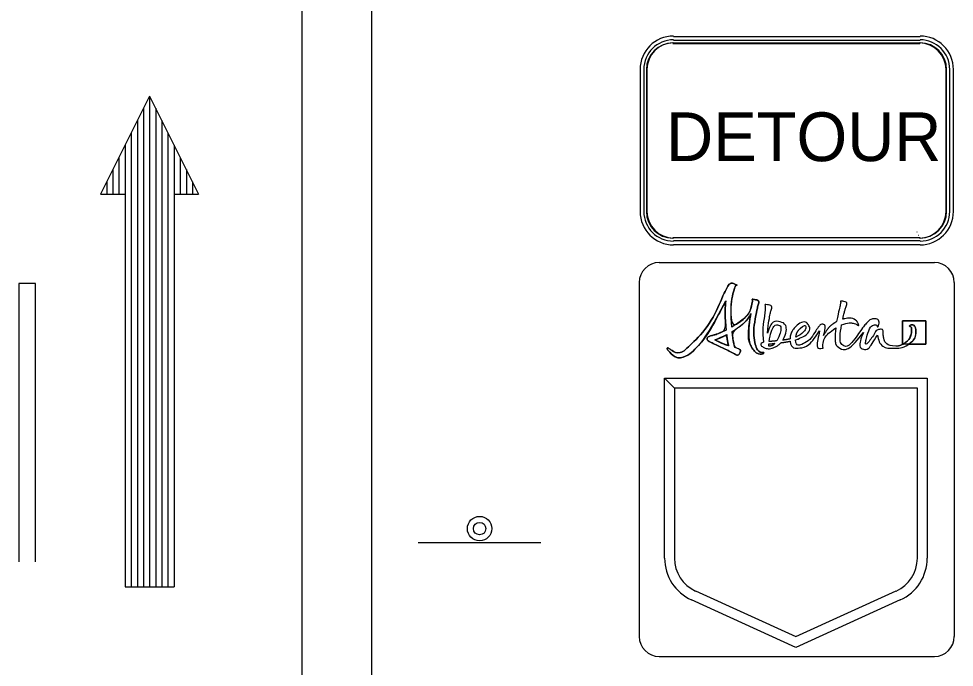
# Model space of a CAD drawing. Extents: x 1806 to 2022, y 110 to 389.
# Drawn here: x 1969.34 to 1985.61, y 233.48 to 244.76 of the extents above; entities that cross this region are included whole.
import ezdxf

# ---------------------------------------------------------------- set-up
doc = ezdxf.new("R2010")
doc.units = 0
for name, color, linetype in [('Level 10', 7, 'Continuous'), ('Level 2', 7, 'Continuous'), ('Level 44', 7, 'Continuous'), ('Level 50', 7, 'Continuous'), ('Level 53', 7, 'Continuous')]:
    doc.layers.add(name, color=color, linetype=linetype)

msp = doc.modelspace()

# ---------------------------------------------------------------- linework, layer by layer
at = {"layer": 'Level 10'}
for p, q in [((1974.267, 233.074), (1974.267, 272.1)), ((1975.477, 233.074), (1975.477, 272.1))]:
    msp.add_line(p, q, dxfattribs=at)
at = {"layer": 'Level 2'}
for p, q in [((1980.475, 240.516), (1985.26, 240.516)), ((1980.475, 240.516), (1985.26, 240.516)), ((1969.337, 240.152), (1969.337, 235.314)), ((1969.627, 240.152), (1969.337, 240.152)), ((1969.627, 235.314), (1969.627, 240.152)), ((1980.128, 240.169), (1980.128, 234.014)), ((1985.607, 240.169), (1985.607, 234.014)), ((1980.57, 235.376), (1980.57, 238.504)), ((1980.57, 238.504), (1980.742, 238.332)), ((1980.742, 238.332), (1980.57, 238.504)), ((1980.57, 238.504), (1985.136, 238.504)), ((1985.136, 238.504), (1985.136, 235.376)), ((1980.742, 238.332), (1980.742, 235.376)), ((1984.965, 238.332), (1980.742, 238.332)), ((1984.965, 235.376), (1984.965, 238.332)), ((1981.109, 234.805), (1982.853, 234.012)), ((1982.853, 234.012), (1984.597, 234.805)), ((1982.853, 233.824), (1981.039, 234.649)), ((1984.668, 234.649), (1982.853, 233.824)), ((1980.475, 233.667), (1985.26, 233.667))]:
    msp.add_line(p, q, dxfattribs=at)
for centre, radius, start, end in [((1980.475, 240.169), 0.347, 90, 180), ((1985.26, 240.169), 0.347, 0, 90), ((1981.369, 235.376), 0.799, 180, 245.5432), ((1981.369, 235.376), 0.628, 180, 245.5432), ((1984.337, 235.376), 0.628, 294.4568, 0), ((1984.337, 235.376), 0.799, 294.4568, 0), ((1980.475, 234.014), 0.347, 180, 270), ((1985.26, 234.014), 0.347, 270, 0)]:
    msp.add_arc(centre, radius, start, end, dxfattribs=at)
at = {"layer": 'Level 44'}
for p, q in [((1980.724, 244.449), (1985.015, 244.449)), ((1980.724, 244.384), (1985.015, 244.384)), ((1980.714, 244.328), (1985.005, 244.328)), ((1980.72, 244.336), (1985.011, 244.336)), ((1980.724, 244.33), (1985.015, 244.33)), ((1980.724, 244.33), (1985.015, 244.33)), ((1980.149, 241.409), (1980.149, 243.874)), ((1980.214, 241.409), (1980.214, 243.874)), ((1980.258, 241.407), (1980.258, 243.872)), ((1980.268, 241.409), (1980.268, 243.874)), ((1980.268, 241.409), (1980.268, 243.874)), ((1980.268, 241.409), (1980.268, 243.874)), ((1985.457, 243.872), (1985.457, 241.407)), ((1985.467, 243.874), (1985.467, 241.409)), ((1985.467, 243.874), (1985.467, 241.409)), ((1985.467, 243.874), (1985.467, 241.409)), ((1985.521, 243.874), (1985.521, 241.409)), ((1985.586, 243.874), (1985.586, 241.409)), ((1984.958, 241.05), (1984.962, 241.052)), ((1984.987, 240.992), (1984.991, 240.994)), ((1985.005, 240.944), (1980.714, 240.944)), ((1985.015, 240.946), (1980.724, 240.946)), ((1985.015, 240.946), (1980.724, 240.946)), ((1985.015, 240.946), (1980.724, 240.946)), ((1985.015, 240.892), (1980.724, 240.892)), ((1985.015, 240.827), (1980.724, 240.827)), ((1983.08, 240.938), (1983.08, 240.938)), ((1983.09, 240.94), (1983.09, 240.94)), ((1983.09, 240.94), (1983.09, 240.94)), ((1983.09, 240.94), (1983.09, 240.94)), ((1985.011, 240.944), (1985.015, 240.946)), ((1976.282, 235.651), (1978.415, 235.651))]:
    msp.add_line(p, q, dxfattribs=at)
for radius in [0.213, 0.107]:
    msp.add_circle((1977.353, 235.889), radius, dxfattribs=at)
for centre, radius, start, end in [((1980.724, 243.875), 0.581, 90, 180), ((1980.724, 243.875), 0.516, 90, 180), ((1985.011, 243.875), 0.581, 0, 90), ((1985.011, 243.875), 0.516, 0, 90), ((1980.714, 243.873), 0.462, 90, 180), ((1980.724, 243.875), 0.462, 90, 180), ((1980.724, 243.875), 0.462, 90, 180), ((1980.724, 243.875), 0.462, 90, 180), ((1985.001, 243.873), 0.462, 0, 90), ((1985.011, 243.875), 0.462, 0, 90), ((1985.011, 243.875), 0.462, 0, 90), ((1985.011, 243.875), 0.462, 0, 90), ((1980.724, 241.405), 0.581, 180, 270), ((1980.724, 241.405), 0.516, 180, 270), ((1980.714, 241.403), 0.462, 180, 270), ((1980.724, 241.405), 0.462, 180, 270), ((1980.724, 241.405), 0.462, 180, 270), ((1980.724, 241.405), 0.462, 180, 270), ((1985.001, 241.403), 0.462, 270, 0), ((1985.011, 241.405), 0.462, 270, 0), ((1985.011, 241.405), 0.462, 270, 0), ((1985.011, 241.405), 0.581, 270, 0), ((1985.011, 241.405), 0.516, 270, 0), ((1985.011, 241.405), 0.462, 270, 0)]:
    msp.add_arc(centre, radius, start, end, dxfattribs=at)
at = {"layer": 'Level 50'}
for p, q in [((1971.613, 243.413), (1970.76, 241.706)), ((1971.613, 243.413), (1971.613, 234.88)), ((1971.613, 243.413), (1972.466, 241.706)), ((1971.507, 243.199), (1971.507, 234.88)), ((1971.72, 243.199), (1971.72, 234.88)), ((1971.4, 242.986), (1971.4, 234.88)), ((1971.827, 242.986), (1971.827, 234.88)), ((1971.293, 242.773), (1971.293, 234.88)), ((1971.933, 242.773), (1971.933, 234.88)), ((1971.187, 242.559), (1971.187, 234.88)), ((1972.04, 242.559), (1972.04, 234.88)), ((1971.08, 242.346), (1971.08, 241.706)), ((1972.146, 242.346), (1972.146, 241.706)), ((1970.973, 242.133), (1970.973, 241.706)), ((1972.253, 242.133), (1972.253, 241.706)), ((1970.867, 241.919), (1970.867, 241.706)), ((1972.36, 241.919), (1972.36, 241.706)), ((1970.76, 241.706), (1971.187, 241.706)), ((1971.187, 241.706), (1971.187, 234.88)), ((1972.04, 241.706), (1972.04, 234.88)), ((1972.04, 241.706), (1972.466, 241.706)), ((1971.187, 234.88), (1972.04, 234.88))]:
    msp.add_line(p, q, dxfattribs=at)
at = {"layer": 'Level 53'}
msp.add_line((1984.816, 239.099), (1984.716, 239.099), dxfattribs=at)
msp.add_lwpolyline([(1984.816, 239.099), (1985.111, 239.099), (1985.111, 239.506), (1984.704, 239.506), (1984.704, 239.099), (1984.716, 239.099)], dxfattribs=at)
for points, degree in [([(1982.262, 238.951), (1982.218, 238.958), (1982.161, 239.017), (1982.143, 239.115), (1982.112, 239.292), (1982.131, 239.466), (1982.183, 239.726), (1982.192, 239.775), (1982.226, 239.86), (1982.119, 239.876), (1982.085, 239.881), (1982.103, 239.865), (1982.093, 239.82), (1982.053, 239.626), (1981.894, 239.487), (1981.736, 239.394), (1981.719, 239.615), (1981.726, 239.861), (1981.768, 240.012), (1981.803, 240.139), (1981.845, 240.115), (1981.793, 240.142), (1981.738, 240.17), (1981.679, 240.133), (1981.632, 240.038), (1981.585, 239.944), (1981.366, 239.429), (1981.017, 239.082), (1980.838, 238.905), (1980.677, 238.996), (1980.644, 239.023), (1980.618, 239.046), (1980.608, 239.011), (1980.641, 238.976), (1980.786, 238.82), (1980.997, 238.91), (1981.073, 238.987), (1981.286, 239.199), (1981.533, 239.656), (1981.633, 239.85), (1981.623, 239.741), (1981.62, 239.557), (1981.641, 239.343), (1981.532, 239.29), (1981.436, 239.259), (1981.39, 239.247), (1981.34, 239.234), (1981.31, 239.214), (1981.309, 239.191), (1981.308, 239.166), (1981.341, 239.145), (1981.389, 239.122), (1981.475, 239.081), (1981.725, 238.963), (1981.787, 238.927), (1981.84, 238.896), (1981.866, 238.92), (1981.881, 238.954), (1981.902, 238.997), (1981.846, 239.022), (1981.791, 239.038), (1981.77, 239.111), (1981.754, 239.208), (1981.743, 239.316), (1981.87, 239.394), (1981.995, 239.499), (1982.068, 239.629), (1982.049, 239.52), (1982.003, 239.149), (1982.12, 238.993), (1982.146, 238.958), (1982.203, 238.92), (1982.258, 238.926), (1982.284, 238.929), (1982.298, 238.946), (1982.295, 238.951), (1982.292, 238.957), (1982.277, 238.949), (1982.262, 238.951)], 3), ([(1981.736, 239.394), (1981.719, 239.615), (1981.726, 239.861), (1981.768, 240.012), (1981.803, 240.139), (1981.845, 240.115), (1981.793, 240.142), (1981.738, 240.17), (1981.679, 240.133), (1981.632, 240.038), (1981.585, 239.944), (1981.366, 239.429), (1981.017, 239.082), (1980.838, 238.905), (1980.677, 238.996), (1980.644, 239.023), (1980.618, 239.046), (1980.608, 239.011), (1980.641, 238.976), (1980.786, 238.82), (1980.997, 238.91), (1981.073, 238.987), (1981.286, 239.199), (1981.533, 239.656), (1981.633, 239.85)], 3), ([(1981.633, 239.85), (1981.623, 239.741), (1981.62, 239.557), (1981.641, 239.343)], 2), ([(1982.262, 238.951), (1982.218, 238.958), (1982.161, 239.017), (1982.143, 239.115), (1982.112, 239.292), (1982.131, 239.466), (1982.183, 239.726), (1982.192, 239.775), (1982.226, 239.86), (1982.119, 239.876), (1982.085, 239.881), (1982.103, 239.865), (1982.093, 239.82), (1982.053, 239.626), (1981.894, 239.487), (1981.736, 239.394)], 3), ([(1983.667, 239.532), (1983.678, 239.587), (1983.692, 239.642), (1983.707, 239.696), (1983.721, 239.745), (1983.761, 239.83), (1983.656, 239.846), (1983.623, 239.851), (1983.637, 239.835), (1983.626, 239.79), (1983.605, 239.706), (1983.58, 239.598), (1983.561, 239.489)], 3), ([(1982.36, 239.288), (1982.368, 239.391), (1982.385, 239.518), (1982.408, 239.635), (1982.418, 239.684), (1982.452, 239.769), (1982.345, 239.786), (1982.311, 239.791), (1982.317, 239.775), (1982.319, 239.729), (1982.323, 239.668), (1982.255, 239.295), (1982.291, 239.132)], 3), ([(1981.743, 239.316), (1981.87, 239.394), (1981.995, 239.499), (1982.068, 239.629)], 2), ([(1982.068, 239.629), (1982.049, 239.52), (1982.003, 239.149), (1982.12, 238.993), (1982.146, 238.958), (1982.203, 238.92), (1982.258, 238.926), (1982.284, 238.929), (1982.298, 238.946), (1982.295, 238.951), (1982.292, 238.957), (1982.277, 238.949), (1982.262, 238.951)], 3), ([(1982.623, 239.167), (1982.698, 239.29), (1982.692, 239.456), (1982.581, 239.484), (1982.452, 239.516), (1982.387, 239.391), (1982.36, 239.288)], 3), ([(1984.59, 239.063), (1984.423, 239.063), (1984.379, 239.193), (1984.371, 239.257), (1984.366, 239.3), (1984.375, 239.362), (1984.301, 239.354), (1984.25, 239.348), (1984.203, 239.247), (1984.137, 239.162), (1984.081, 239.09), (1984.056, 239.096), (1984.069, 239.159), (1984.085, 239.237), (1984.151, 239.421), (1984.225, 239.434), (1984.26, 239.44), (1984.272, 239.38), (1984.288, 239.418), (1984.304, 239.456), (1984.289, 239.538), (1984.212, 239.538), (1984.158, 239.538), (1984.093, 239.48), (1984.04, 239.415), (1983.993, 239.358), (1983.759, 239.013), (1983.66, 239.087), (1983.614, 239.122), (1983.618, 239.264), (1983.647, 239.431)], 3), ([(1983.647, 239.431), (1983.764, 239.476), (1983.861, 239.462), (1983.916, 239.435), (1983.943, 239.422), (1983.947, 239.424), (1983.935, 239.454), (1983.918, 239.498), (1983.824, 239.566), (1983.677, 239.535), (1983.674, 239.534), (1983.67, 239.533), (1983.667, 239.532)], 3), ([(1984.704, 239.506), (1984.704, 239.506), (1984.704, 239.099), (1984.704, 239.099), (1984.704, 239.099), (1984.716, 239.099), (1984.716, 239.099), (1984.804, 239.152), (1984.863, 239.253), (1984.863, 239.336), (1984.863, 239.408), (1984.825, 239.405), (1984.829, 239.415), (1984.842, 239.444), (1984.932, 239.427), (1984.937, 239.326), (1984.941, 239.239), (1984.896, 239.156), (1984.816, 239.099), (1984.816, 239.099), (1985.111, 239.099), (1985.111, 239.099), (1985.111, 239.099), (1985.111, 239.506), (1985.111, 239.506), (1985.111, 239.506), (1984.704, 239.506), (1984.704, 239.506)], 3), ([(1981.641, 239.343), (1981.532, 239.29), (1981.436, 239.259), (1981.39, 239.247), (1981.34, 239.234), (1981.31, 239.214), (1981.309, 239.191), (1981.308, 239.166), (1981.341, 239.145), (1981.389, 239.122), (1981.475, 239.081), (1981.725, 238.963), (1981.787, 238.927), (1981.84, 238.896), (1981.866, 238.92), (1981.881, 238.954), (1981.902, 238.997), (1981.846, 239.022), (1981.791, 239.038)], 3), ([(1982.387, 239.143), (1982.405, 239.274), (1982.473, 239.456), (1982.557, 239.426), (1982.606, 239.41), (1982.581, 239.256), (1982.518, 239.155)], 3), ([(1982.846, 239.171), (1982.864, 239.176), (1982.88, 239.182), (1982.893, 239.188), (1983.054, 239.259), (1983.11, 239.367), (1983.069, 239.433), (1983.03, 239.495), (1982.919, 239.476), (1982.831, 239.384), (1982.788, 239.338), (1982.754, 239.26), (1982.75, 239.188)], 3), ([(1983.335, 239.247), (1983.345, 239.297), (1983.361, 239.353), (1983.362, 239.391), (1983.363, 239.43), (1983.336, 239.439), (1983.325, 239.442), (1983.302, 239.449), (1983.275, 239.437), (1983.247, 239.399), (1983.182, 239.308), (1983.101, 239.164), (1982.977, 239.104), (1982.888, 239.06), (1982.849, 239.104), (1982.846, 239.171)], 3), ([(1982.933, 239.375), (1982.987, 239.425), (1983.014, 239.422), (1983.021, 239.408), (1983.036, 239.379), (1982.972, 239.277), (1982.851, 239.22)], 3), ([(1982.851, 239.22), (1982.861, 239.276), (1982.89, 239.336), (1982.933, 239.375)], 2), ([(1983.26, 239.327), (1983.25, 239.229), (1983.186, 239.015), (1983.295, 239.026), (1983.338, 239.03), (1983.319, 239.037), (1983.322, 239.074), (1983.331, 239.203), (1983.439, 239.312), (1983.545, 239.379)], 3), ([(1983.561, 239.489), (1983.475, 239.439), (1983.394, 239.356), (1983.335, 239.247)], 2), ([(1983.545, 239.379), (1983.527, 239.221), (1983.533, 239.08), (1983.605, 239.035), (1983.737, 238.953), (1983.923, 239.17), (1984.026, 239.303)], 3), ([(1984.716, 239.099), (1984.804, 239.152), (1984.863, 239.253), (1984.863, 239.336), (1984.863, 239.408), (1984.825, 239.405), (1984.829, 239.415), (1984.842, 239.444), (1984.932, 239.427), (1984.937, 239.326), (1984.941, 239.239), (1984.896, 239.156), (1984.816, 239.099)], 3), ([(1981.445, 239.173), (1981.502, 239.193), (1981.573, 239.223), (1981.649, 239.263)], 2), ([(1981.445, 239.173), (1981.502, 239.193), (1981.573, 239.223), (1981.649, 239.263), (1981.659, 239.177), (1981.67, 239.114), (1981.683, 239.068), (1981.627, 239.088), (1981.548, 239.12), (1981.445, 239.173)], 3), ([(1981.683, 239.068), (1981.627, 239.088), (1981.548, 239.12), (1981.445, 239.173)], 2), ([(1981.649, 239.263), (1981.659, 239.177), (1981.67, 239.114), (1981.683, 239.068)], 2), ([(1981.791, 239.038), (1981.77, 239.111), (1981.754, 239.208), (1981.743, 239.316)], 2), ([(1982.75, 239.188), (1982.713, 239.18), (1982.67, 239.173), (1982.623, 239.167)], 2), ([(1982.752, 239.148), (1982.76, 239.076), (1982.807, 239.021), (1982.916, 239.031), (1983.071, 239.046), (1983.208, 239.236), (1983.26, 239.327)], 3), ([(1984.026, 239.303), (1983.974, 239.185), (1983.944, 239.034), (1984.023, 239.011), (1984.115, 238.984), (1984.188, 239.137), (1984.273, 239.254)], 3), ([(1984.273, 239.254), (1984.283, 239.17), (1984.339, 239.025), (1984.564, 239.025), (1984.666, 239.025), (1984.752, 239.054), (1984.816, 239.099)], 3), ([(1982.291, 239.132), (1982.245, 239.117), (1982.226, 239.082), (1982.285, 239.046), (1982.326, 239.021), (1982.415, 239.013), (1982.506, 239.057), (1982.538, 239.073), (1982.566, 239.096), (1982.59, 239.122)], 3), ([(1982.374, 239.064), (1982.38, 239.069), (1982.383, 239.077), (1982.383, 239.085), (1982.383, 239.091), (1982.383, 239.097), (1982.384, 239.103)], 3), ([(1982.411, 239.065), (1982.396, 239.062), (1982.383, 239.062), (1982.374, 239.064)], 2), ([(1982.384, 239.103), (1982.407, 239.104), (1982.443, 239.106), (1982.485, 239.11)], 2), ([(1982.518, 239.155), (1982.477, 239.15), (1982.433, 239.147), (1982.387, 239.143)], 2), ([(1982.485, 239.11), (1982.463, 239.086), (1982.438, 239.069), (1982.411, 239.065)], 2), ([(1982.59, 239.122), (1982.643, 239.129), (1982.7, 239.138), (1982.752, 239.148)], 2), ([(1984.716, 239.099), (1984.678, 239.077), (1984.635, 239.063), (1984.59, 239.063)], 2)]:
    msp.add_open_spline(points, degree=degree, dxfattribs=at)

# ---------------------------------------------------------------- texts
at = {"layer": 'Level 44'}
msp.add_text('DETOUR', height=0.8479, rotation=360, dxfattribs=at).set_placement((1980.595, 242.28))

doc.saveas('drawing.dxf')
